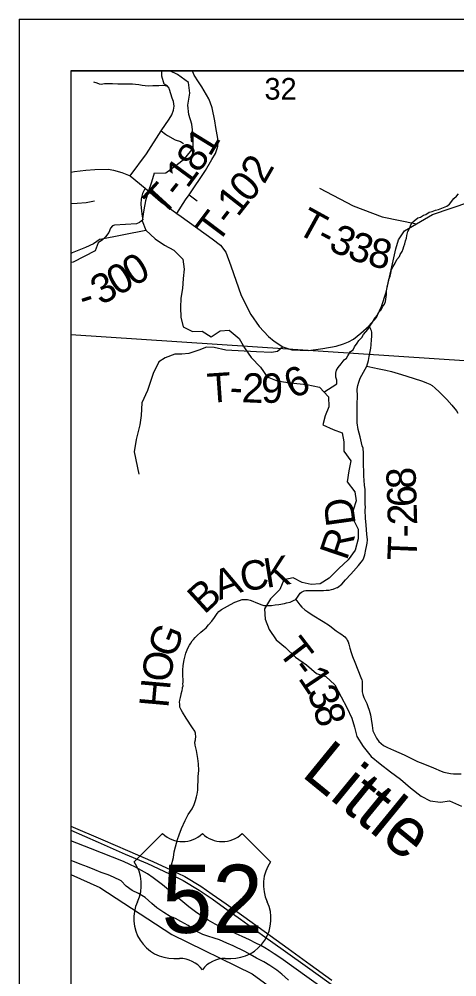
# Model space of a CAD drawing. Extents: x 0 to 45.4, y -2.2 to 22.
# Drawn here: x 2 to 2.846, y 19.147 to 21 of the extents above; entities that cross this region are included whole.
import ezdxf

# ---------------------------------------------------------------- set-up
doc = ezdxf.new("R2010")
doc.units = 0
for name, color, linetype in [('GM_X_Corporation', 7, 'Continuous'), ('GM_X_Major_River', 7, 'Continuous'), ('GM_X_Minor_River', 7, 'Continuous'), ('GM_X_Minor_River_Text', 7, 'Continuous'), ('GM_X_Rail_Line', 7, 'Continuous'), ('GM_X_Section_Text', 7, 'Continuous'), ('GM_X_State_Route', 7, 'Continuous'), ('GM_X_Township_Road', 7, 'Continuous'), ('GM_X_Township_Road_Text', 7, 'Continuous'), ('GM_X_US_Location', 7, 'Continuous'), ('GM_X_US_Route', 7, 'Continuous'), ('GM_X_US_Shield', 7, 'Continuous'), ('SH_Data', 7, 'Continuous')]:
    doc.layers.add(name, color=color, linetype=linetype)

msp = doc.modelspace()

# ---------------------------------------------------------------- linework, layer by layer
at = {"layer": 'GM_X_Corporation'}
for points in [[(8.9, 20.9), (2.1, 20.9), (2.1, 19.3454), (2.1562, 19.32), (2.2951, 19.2289), (2.4503, 19.1527), (2.5862, 19.0536)], [(6.2942, 20.9), (2.1, 20.9), (2.1, 19.3454), (2.1562, 19.32), (2.2951, 19.2289), (2.4503, 19.1527), (2.5862, 19.0536)]]:
    msp.add_lwpolyline(points, dxfattribs=at)
msp.add_lwpolyline([(2.9697, 20.9), (2.1, 20.9), (2.1, 20.3896), (2.9392, 20.3345), (2.9438, 20.419)], close=True, dxfattribs=at)
at = {"layer": 'GM_X_Major_River'}
for points in [[(2.1585, 19.3491), (2.146, 19.354), (2.132, 19.3597), (2.118, 19.365), (2.107, 19.3695), (2.1, 19.3721)], [(2.5204, 19.1406), (2.5079, 19.1524), (2.4981, 19.1604), (2.4845, 19.1691), (2.4732, 19.1759), (2.4588, 19.1835), (2.4463, 19.1904), (2.4365, 19.196), (2.4138, 19.2074), (2.4013, 19.2124), (2.387, 19.2188), (2.3771, 19.2219), (2.3647, 19.2256), (2.3548, 19.2291), (2.3412, 19.2363), (2.3265, 19.2465), (2.3125, 19.2545), (2.3019, 19.2598), (2.2921, 19.264), (2.2796, 19.2716), (2.2664, 19.281), (2.2565, 19.289), (2.2433, 19.3008), (2.2308, 19.3084), (2.2187, 19.3141), (2.2066, 19.3228), (2.1975, 19.3326), (2.1822, 19.3397), (2.1722, 19.3446), (2.1585, 19.3491)]]:
    msp.add_lwpolyline(points, dxfattribs=at)
at = {"layer": 'GM_X_Minor_River'}
msp.add_line((2.1567, 20.5742), (2.2449, 20.592), dxfattribs=at)
for points in [[(2.2612, 20.7023), (2.2838, 20.7024), (2.3028, 20.7168), (2.3202, 20.7304), (2.3362, 20.7501), (2.3362, 20.7751), (2.334, 20.7971), (2.328, 20.8153), (2.3258, 20.8335), (2.3297, 20.857), (2.3275, 20.8775), (2.3063, 20.8927), (2.2913, 20.9)], [(2.2612, 20.7023), (2.2559, 20.6846), (2.2497, 20.6656), (2.2443, 20.6482), (2.2412, 20.6308), (2.2381, 20.6095), (2.2449, 20.592), (2.263, 20.5753), (2.2811, 20.563), (2.2992, 20.5531), (2.3166, 20.5356), (2.3188, 20.5166), (2.3172, 20.4984), (2.3156, 20.4787), (2.3125, 20.4605), (2.3116, 20.4422), (2.3123, 20.4233), (2.3168, 20.405), (2.3349, 20.3958), (2.3539, 20.3965), (2.3712, 20.3851), (2.3887, 20.3972), (2.4061, 20.3986), (2.425, 20.3819), (2.4355, 20.3644), (2.4483, 20.3453), (2.4664, 20.327), (2.4792, 20.308), (2.4989, 20.3004), (2.5193, 20.2972), (2.5367, 20.2949), (2.5564, 20.2933), (2.5806, 20.2879), (2.5979, 20.2696), (2.5986, 20.2499), (2.5917, 20.2325), (2.5871, 20.215), (2.6068, 20.2058), (2.6242, 20.1997), (2.6279, 20.1822), (2.6278, 20.164), (2.6414, 20.1457), (2.6375, 20.126), (2.6344, 20.1048), (2.6487, 20.0857), (2.6516, 20.0683), (2.6455, 20.0501), (2.6454, 20.0326), (2.6552, 20.0136), (2.6551, 19.9946), (2.6497, 19.9726), (2.636, 19.9537), (2.6178, 19.9371), (2.5995, 19.9182), (2.582, 19.9076), (2.5646, 19.9061), (2.5472, 19.91), (2.5298, 19.9192), (2.5116, 19.9154), (2.504, 19.8965), (2.4857, 19.8783), (2.4743, 19.8594), (2.4757, 19.8389), (2.4832, 19.8191), (2.4968, 19.7994), (2.5149, 19.7841), (2.5345, 19.7658), (2.5556, 19.7506), (2.5745, 19.7338), (2.5926, 19.7284), (2.61, 19.7124), (2.6228, 19.6888), (2.6333, 19.6683), (2.6431, 19.6478), (2.6483, 19.6303), (2.6528, 19.612), (2.6648, 19.593), (2.6806, 19.5732), (2.698, 19.5595), (2.7176, 19.5435), (2.7372, 19.5298), (2.7568, 19.513), (2.7772, 19.497), (2.7946, 19.4878), (2.8143, 19.4854), (2.8317, 19.4877), (2.8552, 19.4777)], [(2.5888, 20.2784), (2.614, 20.2942), (2.6141, 20.3014), (2.6123, 20.3071), (2.6121, 20.3151), (2.6133, 20.3211), (2.6168, 20.326), (2.6226, 20.3331), (2.6284, 20.3406), (2.633, 20.3443), (2.6354, 20.3485), (2.6408, 20.3567), (2.6454, 20.3601), (2.6482, 20.3661), (2.6536, 20.3732), (2.6564, 20.3785), (2.6622, 20.3841), (2.6657, 20.3901), (2.6738, 20.3998), (2.6781, 20.4062), (2.6827, 20.4126), (2.6855, 20.419), (2.6921, 20.4265), (2.6944, 20.4325), (2.6998, 20.4377), (2.7026, 20.4434), (2.7065, 20.4486), (2.7081, 20.4539), (2.7094, 20.463), (2.7102, 20.4676), (2.7103, 20.4736), (2.7116, 20.4816), (2.7136, 20.4899), (2.7149, 20.4963), (2.7169, 20.5028), (2.7185, 20.5088), (2.7201, 20.5156), (2.7233, 20.5213), (2.7268, 20.5277), (2.7303, 20.5352), (2.735, 20.5408), (2.7366, 20.545), (2.7405, 20.5506), (2.7421, 20.5559), (2.7437, 20.5604), (2.7453, 20.5653), (2.7469, 20.571), (2.7489, 20.5766), (2.7497, 20.5812), (2.7514, 20.5891), (2.7545, 20.5952), (2.7565, 20.6004), (2.7592, 20.6061), (2.7635, 20.6098), (2.7704, 20.6154), (2.7757, 20.6172), (2.7818, 20.6209), (2.7864, 20.6223), (2.7925, 20.6264), (2.7986, 20.6278), (2.8051, 20.6307), (2.8108, 20.6318), (2.8204, 20.6358), (2.8265, 20.638), (2.8318, 20.6421), (2.8404, 20.6533), (2.8454, 20.6578), (2.8492, 20.6619)], [(2.1567, 20.5742), (2.1439, 20.5655), (2.1284, 20.5582), (2.1027, 20.5476), (2.1, 20.5468)]]:
    msp.add_lwpolyline(points, dxfattribs=at)
at = {"layer": 'GM_X_Rail_Line'}
msp.add_lwpolyline([(2.7294, 19.0226), (2.5058, 19.1832), (2.4931, 19.1918), (2.4833, 19.198), (2.4747, 19.2031), (2.4669, 19.2076), (2.4576, 19.2126), (2.4455, 19.2186), (2.411, 19.234), (2.3917, 19.2428), (2.3792, 19.2492), (2.3651, 19.2569), (2.3529, 19.2643), (2.3408, 19.2731), (2.3279, 19.2827), (2.277, 19.3254), (2.2589, 19.3385), (2.2478, 19.3463), (2.2366, 19.353), (2.225, 19.3594), (2.214, 19.3648), (2.2019, 19.3702), (2.1382, 19.3954), (2.1, 19.4104)], dxfattribs=at)
at = {"layer": 'GM_X_State_Route'}
for points in [[(2.7682, 20.604), (2.799, 20.6223), (2.8714, 20.6464), (2.9172, 20.6576), (2.9859, 20.6973), (3.015, 20.7125), (3.0417, 20.7277), (3.0797, 20.7405), (3.1523, 20.7541), (3.1983, 20.7669), (3.215, 20.7739), (3.2746, 20.8141), (3.2862, 20.8231), (3.3045, 20.8374), (3.3476, 20.8709), (3.3845, 20.8987), (3.387, 20.9)], [(2.1, 20.7039), (2.1072, 20.7055), (2.1288, 20.7079), (2.1465, 20.7091), (2.1726, 20.71), (2.1825, 20.708), (2.1983, 20.7034), (2.2144, 20.697), (2.2436, 20.6728), (2.2735, 20.6474), (2.3051, 20.6239), (2.313, 20.6182)], [(2.313, 20.6182), (2.3733, 20.5753), (2.389, 20.5629), (2.3998, 20.5494), (2.4091, 20.5229), (2.4289, 20.4653), (2.4478, 20.4289), (2.4637, 20.4051), (2.4818, 20.3861), (2.4929, 20.3767), (2.5094, 20.3662), (2.5272, 20.3602), (2.5594, 20.3588), (2.5872, 20.3625), (2.6131, 20.3675), (2.6269, 20.3719), (2.6369, 20.3756), (2.6462, 20.381), (2.6603, 20.3925), (2.6768, 20.4068), (2.6906, 20.4227), (2.6927, 20.4274)], [(2.6927, 20.4274), (2.7003, 20.4438), (2.7094, 20.4715), (2.7284, 20.5557), (2.7334, 20.5728), (2.7448, 20.5902), (2.7526, 20.5948), (2.7682, 20.604)]]:
    msp.add_lwpolyline(points, dxfattribs=at)
at = {"layer": 'GM_X_Township_Road'}
msp.add_line((2.3286, 20.6602), (2.3442, 20.6488), dxfattribs=at)
for points in [[(2.2905, 20.8639), (2.2897, 20.8665), (2.2869, 20.8702), (2.2802, 20.8744), (2.2757, 20.8895), (2.2756, 20.9)], [(2.3051, 20.6239), (2.3216, 20.6507), (2.3286, 20.6602), (2.3601, 20.7072), (2.3727, 20.7285), (2.3794, 20.7403), (2.383, 20.7496), (2.3841, 20.7543), (2.3849, 20.7606), (2.3838, 20.7693), (2.3805, 20.7906), (2.3782, 20.8034), (2.3729, 20.8283), (2.3691, 20.8393), (2.3666, 20.8461), (2.353, 20.8692), (2.3468, 20.8786), (2.3382, 20.8917), (2.3357, 20.8982), (2.3357, 20.9)], [(2.1439, 20.879), (2.1501, 20.8768), (2.1546, 20.8748), (2.1584, 20.8745), (2.165, 20.8752), (2.1686, 20.8752), (2.174, 20.8755), (2.1806, 20.8752), (2.191, 20.8751), (2.2136, 20.8748), (2.2194, 20.8749), (2.2249, 20.8743), (2.2316, 20.8736), (2.2378, 20.8726), (2.2437, 20.8716), (2.2503, 20.871), (2.2585, 20.8714), (2.2699, 20.8719), (2.2777, 20.8723), (2.2825, 20.8718), (2.2869, 20.8702)], [(2.2144, 20.697), (2.246, 20.7396), (2.2748, 20.7841), (2.2899, 20.8064), (2.2953, 20.8152), (2.2986, 20.8237), (2.2994, 20.8314), (2.2983, 20.8404), (2.2958, 20.8474), (2.2905, 20.8639)], [(2.2748, 20.7841), (2.283, 20.7775), (2.2869, 20.7747), (2.3013, 20.7666), (2.3117, 20.7633), (2.3177, 20.7597)], [(2.2436, 20.6728), (2.2385, 20.6627), (2.2357, 20.6522), (2.2355, 20.6419), (2.2363, 20.6287), (2.2377, 20.619), (2.2392, 20.6118), (2.2326, 20.6067), (2.2267, 20.6043), (2.1845, 20.6017), (2.1803, 20.5999), (2.1766, 20.5957), (2.1731, 20.5874), (2.1671, 20.5786), (2.1612, 20.5733), (2.1526, 20.5672), (2.1472, 20.5515), (2.1042, 20.5297), (2.1, 20.529)], [(2.5803, 20.6731), (2.6455, 20.6387), (2.7019, 20.6176), (2.7682, 20.604)], [(2.1, 20.6436), (2.112, 20.6443), (2.1297, 20.6456), (2.1458, 20.6488)], [(2.535, 19.8771), (2.5382, 19.8819), (2.5418, 19.8877), (2.5433, 19.8896), (2.5455, 19.8916), (2.5483, 19.8929), (2.5512, 19.8939), (2.5539, 19.8944), (2.5582, 19.8949), (2.5798, 19.8949), (2.5884, 19.8948), (2.5936, 19.8951), (2.5996, 19.8954), (2.6039, 19.8964), (2.6073, 19.8974), (2.6113, 19.8989), (2.6149, 19.9004), (2.6153, 19.9006), (2.6238, 19.9067), (2.6311, 19.9152), (2.6412, 19.9265), (2.6463, 19.9318), (2.6558, 19.9429), (2.6611, 19.9492), (2.6645, 19.9535), (2.6652, 19.9549), (2.6662, 19.958), (2.6684, 19.9638), (2.6689, 19.9666), (2.6698, 19.9707), (2.6723, 19.983), (2.6726, 19.9865), (2.6732, 19.9926), (2.6724, 20.0035), (2.6708, 20.0208), (2.6696, 20.0343), (2.6692, 20.05), (2.6693, 20.0557), (2.6689, 20.0614), (2.6691, 20.072), (2.669, 20.082), (2.6691, 20.09), (2.6676, 20.0982), (2.6664, 20.1167), (2.6663, 20.1256), (2.6659, 20.1373), (2.6655, 20.1603), (2.6647, 20.17), (2.663, 20.1742), (2.6594, 20.1916), (2.6552, 20.2059), (2.6537, 20.2189), (2.6537, 20.2345), (2.6535, 20.2545), (2.6539, 20.271), (2.6531, 20.2832), (2.6538, 20.2882), (2.6546, 20.2915), (2.6565, 20.298), (2.6593, 20.3056), (2.6722, 20.3289), (2.6753, 20.3393), (2.6767, 20.3474), (2.6797, 20.3637), (2.6806, 20.3701), (2.6813, 20.3803), (2.6817, 20.3858), (2.6817, 20.389), (2.6817, 20.3916), (2.6815, 20.3941), (2.6809, 20.3967), (2.6797, 20.3997), (2.6768, 20.4068)], [(2.5094, 20.3662), (2.4997, 20.357), (2.4878, 20.3548), (2.4586, 20.3564), (2.3995, 20.3593), (2.3767, 20.365), (2.362, 20.3654), (2.3476, 20.3594), (2.3301, 20.3535), (2.3283, 20.3529), (2.3146, 20.3518), (2.301, 20.3518), (2.282, 20.345), (2.2703, 20.337), (2.2593, 20.3146), (2.2483, 20.2816), (2.2373, 20.2577), (2.2358, 20.2334), (2.2332, 20.2152), (2.2263, 20.1867), (2.2225, 20.1632), (2.2312, 20.1196)], [(2.6722, 20.3289), (2.6837, 20.326), (2.6958, 20.3238), (2.7086, 20.3211), (2.7199, 20.3184), (2.7389, 20.3124), (2.7615, 20.3054), (2.7797, 20.2995), (2.7876, 20.2967), (2.7938, 20.2941), (2.7981, 20.2911), (2.8039, 20.2863), (2.8119, 20.2788), (2.8188, 20.2719), (2.8268, 20.2639), (2.8363, 20.2533), (2.8452, 20.2423), (2.848, 20.238)], [(2.2904, 19.3467), (2.2935, 19.3543), (2.2939, 19.3611), (2.2981, 19.3778), (2.2995, 19.3892), (2.3021, 19.3987), (2.3021, 19.3989), (2.3063, 19.4128), (2.3096, 19.4222), (2.3141, 19.4342), (2.3209, 19.4498), (2.3267, 19.4613), (2.3342, 19.4721), (2.3384, 19.4805), (2.341, 19.4882), (2.3428, 19.4952), (2.344, 19.5009), (2.3454, 19.5081), (2.3462, 19.5345), (2.3471, 19.5466), (2.3465, 19.5591), (2.3455, 19.5698), (2.3427, 19.585), (2.3401, 19.5956), (2.3397, 19.6009), (2.3408, 19.606), (2.3413, 19.6131), (2.3411, 19.6169), (2.3408, 19.6187), (2.3393, 19.6226), (2.3353, 19.6292), (2.3227, 19.6478), (2.3155, 19.659), (2.3129, 19.6639), (2.3108, 19.6692), (2.3103, 19.6745), (2.3101, 19.6785), (2.3105, 19.6824), (2.3116, 19.6879), (2.3132, 19.6936), (2.3133, 19.6945), (2.3153, 19.701), (2.3159, 19.705), (2.316, 19.7069), (2.3168, 19.7102), (2.3166, 19.7143), (2.3169, 19.7171), (2.3166, 19.7342), (2.3165, 19.741), (2.317, 19.7489), (2.3177, 19.7537), (2.3188, 19.7605), (2.3223, 19.7735), (2.3245, 19.7797), (2.3268, 19.7844), (2.3295, 19.7891), (2.3317, 19.793), (2.3345, 19.797), (2.3368, 19.8), (2.34, 19.8036), (2.3443, 19.8078), (2.3515, 19.8141), (2.3552, 19.8171), (2.3613, 19.8222), (2.3663, 19.8279), (2.3727, 19.8355), (2.3778, 19.8427), (2.3825, 19.85), (2.3859, 19.8538), (2.3911, 19.8579), (2.3969, 19.8612), (2.4085, 19.8674), (2.4169, 19.8718), (2.426, 19.8755), (2.4308, 19.877), (2.4359, 19.8775), (2.4411, 19.8772), (2.4463, 19.876), (2.4519, 19.8743), (2.4577, 19.8717), (2.4624, 19.8695), (2.4672, 19.8673), (2.4729, 19.8659), (2.477, 19.8654), (2.4819, 19.8653), (2.4875, 19.8658), (2.4948, 19.8667), (2.5022, 19.8677), (2.5128, 19.8696), (2.5171, 19.8705), (2.5236, 19.8723), (2.5305, 19.8753), (2.535, 19.8771)], [(2.535, 19.8771), (2.5426, 19.8668), (2.5466, 19.8625), (2.552, 19.8572), (2.558, 19.8532), (2.5665, 19.8478), (2.5877, 19.8348), (2.5997, 19.8266), (2.6068, 19.8212), (2.613, 19.8164), (2.6186, 19.8127), (2.6237, 19.8096), (2.6267, 19.8071), (2.6294, 19.8047), (2.6325, 19.8013), (2.6341, 19.7987), (2.636, 19.7953), (2.6373, 19.7907), (2.6394, 19.7829), (2.6416, 19.7747), (2.6444, 19.7669), (2.6488, 19.7558), (2.655, 19.7409), (2.6605, 19.7265), (2.6622, 19.7215), (2.6628, 19.7192), (2.6631, 19.7156), (2.6632, 19.711), (2.6632, 19.7063), (2.6632, 19.7028), (2.6634, 19.6986), (2.6642, 19.6937), (2.6662, 19.6879), (2.6691, 19.6824), (2.6723, 19.6757), (2.6742, 19.6701), (2.6765, 19.6628), (2.679, 19.6543), (2.6808, 19.6457), (2.6822, 19.6335), (2.6829, 19.6282), (2.6837, 19.6234), (2.6862, 19.6181), (2.6881, 19.6142), (2.6908, 19.609), (2.6955, 19.6024), (2.6995, 19.5984), (2.7042, 19.5949), (2.7123, 19.591), (2.7238, 19.5857), (2.7441, 19.5765), (2.7536, 19.5719), (2.7698, 19.564), (2.7805, 19.5597), (2.8012, 19.5513), (2.8156, 19.5448), (2.8207, 19.5433), (2.8273, 19.5418), (2.8341, 19.5404), (2.8396, 19.5402)], [(2.8396, 19.5402), (2.8433, 19.54), (2.8545, 19.5397)]]:
    msp.add_lwpolyline(points, dxfattribs=at)
at = {"layer": 'GM_X_US_Route'}
for points in [[(2.1, 19.4388), (2.1617, 19.4124), (2.2092, 19.3917), (2.2584, 19.3705), (2.2935, 19.3543), (2.32, 19.341), (2.3512, 19.3226), (2.3731, 19.307), (2.4002, 19.2882), (2.4341, 19.2637), (2.4734, 19.2356), (2.5201, 19.2017), (2.5625, 19.1711), (2.6045, 19.1407)], [(2.1, 19.4307), (2.1525, 19.408), (2.2048, 19.3847), (2.2481, 19.3663), (2.2904, 19.3467), (2.3168, 19.3334), (2.3481, 19.3149), (2.3733, 19.2978), (2.3971, 19.2806), (2.428, 19.2587), (2.4703, 19.2279), (2.5147, 19.1965), (2.5575, 19.1656), (2.5988, 19.1361), (2.6483, 19.1006), (2.6861, 19.0735), (2.7238, 19.0463), (2.7549, 19.0241), (2.8309, 18.9705), (2.8814, 18.9354), (2.9802, 18.8671), (3.0375, 18.8275), (3.0908, 18.7902), (3.122, 18.7687)]]:
    msp.add_lwpolyline(points, dxfattribs=at)
at = {"layer": 'GM_X_US_Shield'}
for p, q in [((2.2773, 19.4245), (2.2223, 19.3696)), ((2.486, 19.3696), (2.4311, 19.4245)), ((2.2992, 19.1828), (2.3102, 19.1828)), ((2.3981, 19.1828), (2.4091, 19.1828))]:
    msp.add_line(p, q, dxfattribs=at)
for centre, radius, start, end in [((2.3157, 19.4637), 0.0549, 225.573, 314.427), ((2.3926, 19.4637), 0.0549, 225.573, 314.427), ((2.1593, 19.3254), 0.0769, 334.5471, 35.0009), ((2.549, 19.3254), 0.0769, 144.9991, 205.4529), ((2.2984, 19.2597), 0.0769, 154.8319, 270.6383), ((2.41, 19.2597), 0.0769, 269.3617, 25.1681), ((2.3102, 19.1279), 0.0549, 36.8699, 90), ((2.3981, 19.1279), 0.0549, 90, 143.1301)]:
    msp.add_arc(centre, radius, start, end, dxfattribs=at)
at = {"layer": 'SH_Data'}
for p, q in [((2, 21), (9, 21)), ((2, 21), (2, 14)), ((2.1, 20.9), (2.1, 14.1)), ((2.1, 20.9), (8.9, 20.9))]:
    msp.add_line(p, q, dxfattribs=at)

# ---------------------------------------------------------------- texts
at = {"layer": 'GM_X_Minor_River_Text'}
msp.add_text('Little', height=0.09468, rotation=320.7841, dxfattribs=at).set_placement((2.5435, 19.5371))
at = {"layer": 'GM_X_Section_Text'}
msp.add_text('32', height=0.04186, rotation=0, dxfattribs=at).set_placement((2.4742, 20.8443))
at = {"layer": 'GM_X_Township_Road_Text'}
for s, rotation, p in [('1', 58.4431, (2.3686, 20.7319)), ('8', 55.2501, (2.3467, 20.7002)), ('2', 60.334, (2.4738, 20.679)), ('1', 53.67, (2.325, 20.6707)), ('0', 48.7939, (2.4436, 20.6425)), ('T', 47.5714, (2.2777, 20.6159)), ('-', 51.7578, (2.3093, 20.6507)), ('1', 51.8441, (2.4225, 20.6156)), ('T', 53.015, (2.383, 20.5633)), ('-', 52.8093, (2.4085, 20.5972)), ('T', 331.2495, (2.5333, 20.5879)), ('-', 332.3816, (2.5716, 20.5669)), ('3', 335.7747, (2.5956, 20.5545)), ('3', 340.2828, (2.632, 20.5383)), ('8', 346.2105, (2.6711, 20.5246)), ('0', 31.1571, (2.2215, 20.4814)), ('0', 30.2352, (2.1904, 20.4633)), ('3', 28.3284, (2.1578, 20.4457)), ('-', 17.5317, (2.1248, 20.4341)), ('6', 25.942, (2.5295, 20.2642)), ('T', 3.9835, (2.3654, 20.2574)), ('2', 357.3919, (2.4296, 20.2591)), ('9', 0.8196, (2.4683, 20.2575)), ('-', 357.1165, (2.406, 20.2603)), ('8', 91.9632, (2.7675, 20.0921)), ('6', 91.8867, (2.7687, 20.057)), ('D', 97.9096, (2.6509, 20.0231)), ('2', 91.5319, (2.7696, 20.0217)), ('R', 71.2574, (2.6332, 19.9509)), ('-', 90.9404, (2.77, 19.9977)), ('T', 87.6723, (2.7683, 19.9517)), ('K', 9.0895, (2.4776, 19.8995)), ('A', 19.9975, (2.3873, 19.8756)), ('C', 9.3273, (2.4316, 19.892)), ('B', 42.4546, (2.3579, 19.8471)), ('G', 68.0078, (2.2987, 19.7613)), ('T', 307.6203, (2.4986, 19.7765)), ('O', 82.1361, (2.2928, 19.7154)), ('-', 306.948, (2.5245, 19.743)), ('1', 304.0213, (2.5381, 19.7249)), ('H', 84.8714, (2.2884, 19.6663)), ('3', 290.6231, (2.556, 19.6991)), ('8', 285.4606, (2.5679, 19.6676))]:
    msp.add_text(s, height=0.0568, rotation=rotation, dxfattribs=at).set_placement(p)
at = {"layer": 'GM_X_US_Location'}
for s in ['0', '/']:
    msp.add_text(s, height=0.000189, dxfattribs=at).set_placement((2.3541, 19.2971))
msp.add_text('52', height=0.000189, rotation=0, dxfattribs=at).set_placement((2.315, 19.2579))
at = {"layer": 'GM_X_US_Shield'}
msp.add_text('52', height=0.13184, dxfattribs=at).set_placement((2.2754, 19.2322))

doc.saveas('drawing.dxf')
